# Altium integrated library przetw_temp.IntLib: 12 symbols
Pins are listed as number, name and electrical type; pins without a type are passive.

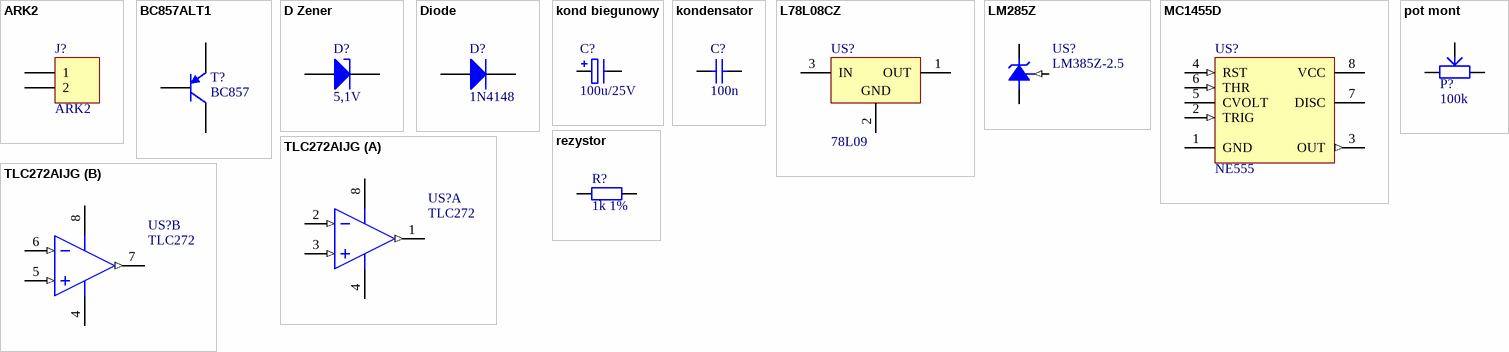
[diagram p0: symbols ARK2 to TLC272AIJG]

## ARK2
designator J?
footprint ARK2 3,5mm
footprint ARK2 5mm
footprint ARK2 7,5mm
pins: 1, 2

## BC857ALT1
designator T?, comment BC857
General Purpose Transistor PNP Silicon
footprint 318-08 (SOT-23; 3 Leads; Body 3.0 x 2.6 mm, inc. leads (LxW max))
simulation model BC857ALT1 (PNP)
signal-integrity model BC857ALT1
pins: 1 B, 2 E, 3 C

## D Zener
designator D?, comment 5,1V
Zener Diode
footprint dioda 10mm
footprint dioda 17,5mm
footprint dioda 7,5mm
footprint dioda MINIMELF (SMT LED; 2 Flat Leads)
pins: 1 A, 2 K

## Diode
designator D?, comment 1N4148
Default Diode
footprint dioda 10mm
footprint dioda 17,5mm
footprint dioda 7,5mm
footprint dioda MINIMELF (SMT LED; 2 Flat Leads)
pins: 1 A, 2 K

## kond biegunowy
designator C?, comment 100u/25V
Polarized Capacitor
footprint Tantal B 3528-1411 (Capacitor, SM Tantalum; Body 3.5 x 2.8 mm (LxW typ))
footprint Tantal C 6032-2412 (Capacitor, SM Tantalum; Body 6.0 x 3.2 mm (LxW typ))
footprint Tantal D 7343-2917 (Capacitor, SM Tantalum; Body 7.3 x 4.3 mm (LxW typ))
footprint 2,5/5mm elektrolit
footprint 3,5/7mm elektrolit
footprint 5/10mm elektrolit
footprint 2,5/7mm elektrolit
footprint 7,5/16mm elektrolit
footprint 5/12,5mm elektrolit
footprint Tantal A 3216-1206 (Capacitor, SM Tantalum; Body 3.2 x 1.6 mm (LxW typ))
footprint A SMD elektrolit
footprint B SMD elektrolit
footprint C SMD elektrolit
footprint D SMD elektrolit
footprint E SMD elektrolit
footprint F SMD elektrolit
footprint 2,5/7mm le抗cy elektrolit
footprint 5/10mm le抗cy elektrolit
pins: 1, 2
1 alternate drawing of the same symbol

## kondensator
designator C?, comment 100n
footprint kond 2,5mm
footprint kond 7,5mm
footprint kond 10mm
footprint MELF-0805 (Metal Electrode Face (MELF) Resistor; Body 2 x 1.4 mm (LxDia))
footprint MELF-1206 (Metal Electrode Face (MELF) Resistor; Body 3.2 x 1.8 mm (LxDia))
footprint kond 15mm
footprint kond 5mm chudy
footprint kond 5mm gruby
footprint kond 5mm sredni
pins: 1, 2

## L78L08CZ
designator US?, comment 78L09
Positive Voltage Regulator
footprint TO92 (TO, Flat Index; 3 In-Line, Axial Leads; Body Dia. 4.8mm; Leads 0.51 x 0.51 mm (max))
pins: 1 OUT (power), 2 GND (power), 3 IN (power)

## LM285Z
designator US?, comment LM385Z-2.5
Adjustable Micropower Voltage Reference; PartNumber: LM285Z; Manufacturer: National Semiconductor; CompType: Voltage Reference IC; PackageTopMarking: NSXYTT*LM285*Z
footprint Z03A (TO, Flat Index; 3 In-Line, Axial Leads; Body Dia. 5mm; Leads 0.55 x 0.50 mm (max))
pins: 1 -V, 2 +V, 3 FB (in)

## MC1455D
designator US?, comment NE555
Timing Circuit
footprint 751-02_N (SOIC, 8-Leads, Body 4.9x3.9mm, Pitch 1.27mm, IPC Medium Density)
footprint 751-02_L (SOIC, 8-Leads, Body 4.9x3.9mm, Pitch 1.27mm, IPC High Density)
footprint 751-02_M (SOIC, 8-Leads, Body 4.9x3.9mm, Pitch 1.27mm, IPC Low Density)
3D model 751-06 (8-Pin Small Outline Integrated Circuit 1.27 mm Pitch)
pins: 1 GND (power), 2 TRIG (in), 3 OUT (out), 4 RST (in), 5 CVOLT, 6 THR (in), 7 DISC (oc), 8 VCC (power)

## pot mont
designator P?, comment 100k
footprint helitrim 5x10mm
footprint pot mont poziom
pins: a, b, c

## rezystor
designator R?, comment 1k 1%
footprint rez 7,5mm
footprint rez 10mm
footprint rez 12,5mm
footprint rez 15mm
footprint rez 17,5mm
footprint MELF-0805 (Metal Electrode Face (MELF) Resistor; Body 2 x 1.4 mm (LxDia))
footprint MELF-1206 (Metal Electrode Face (MELF) Resistor; Body 3.2 x 1.8 mm (LxDia))
footprint rez_bocznik 20mm
footprint rez_5W kostka
pins: 1, 2

## TLC272AIJG
designator US?, comment TLC272
LinCMOS Precision Dual Operational Amplifier
footprint JG008 (DIP; 8 Leads; Row Spacing 7.62 mm; Pitch 2.54 mm)
3D model JG008 (DIP; 8 Leads; Row Spacing 7.62 mm; Pitch 2.54 mm)
pins on every part: 4 GND (power), 8 VDD (power)
part A pins: 1 OUT (out), 2 IN- (in), 3 IN+ (in)
part B pins: 5 IN+ (in), 6 IN- (in), 7 OUT (out)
